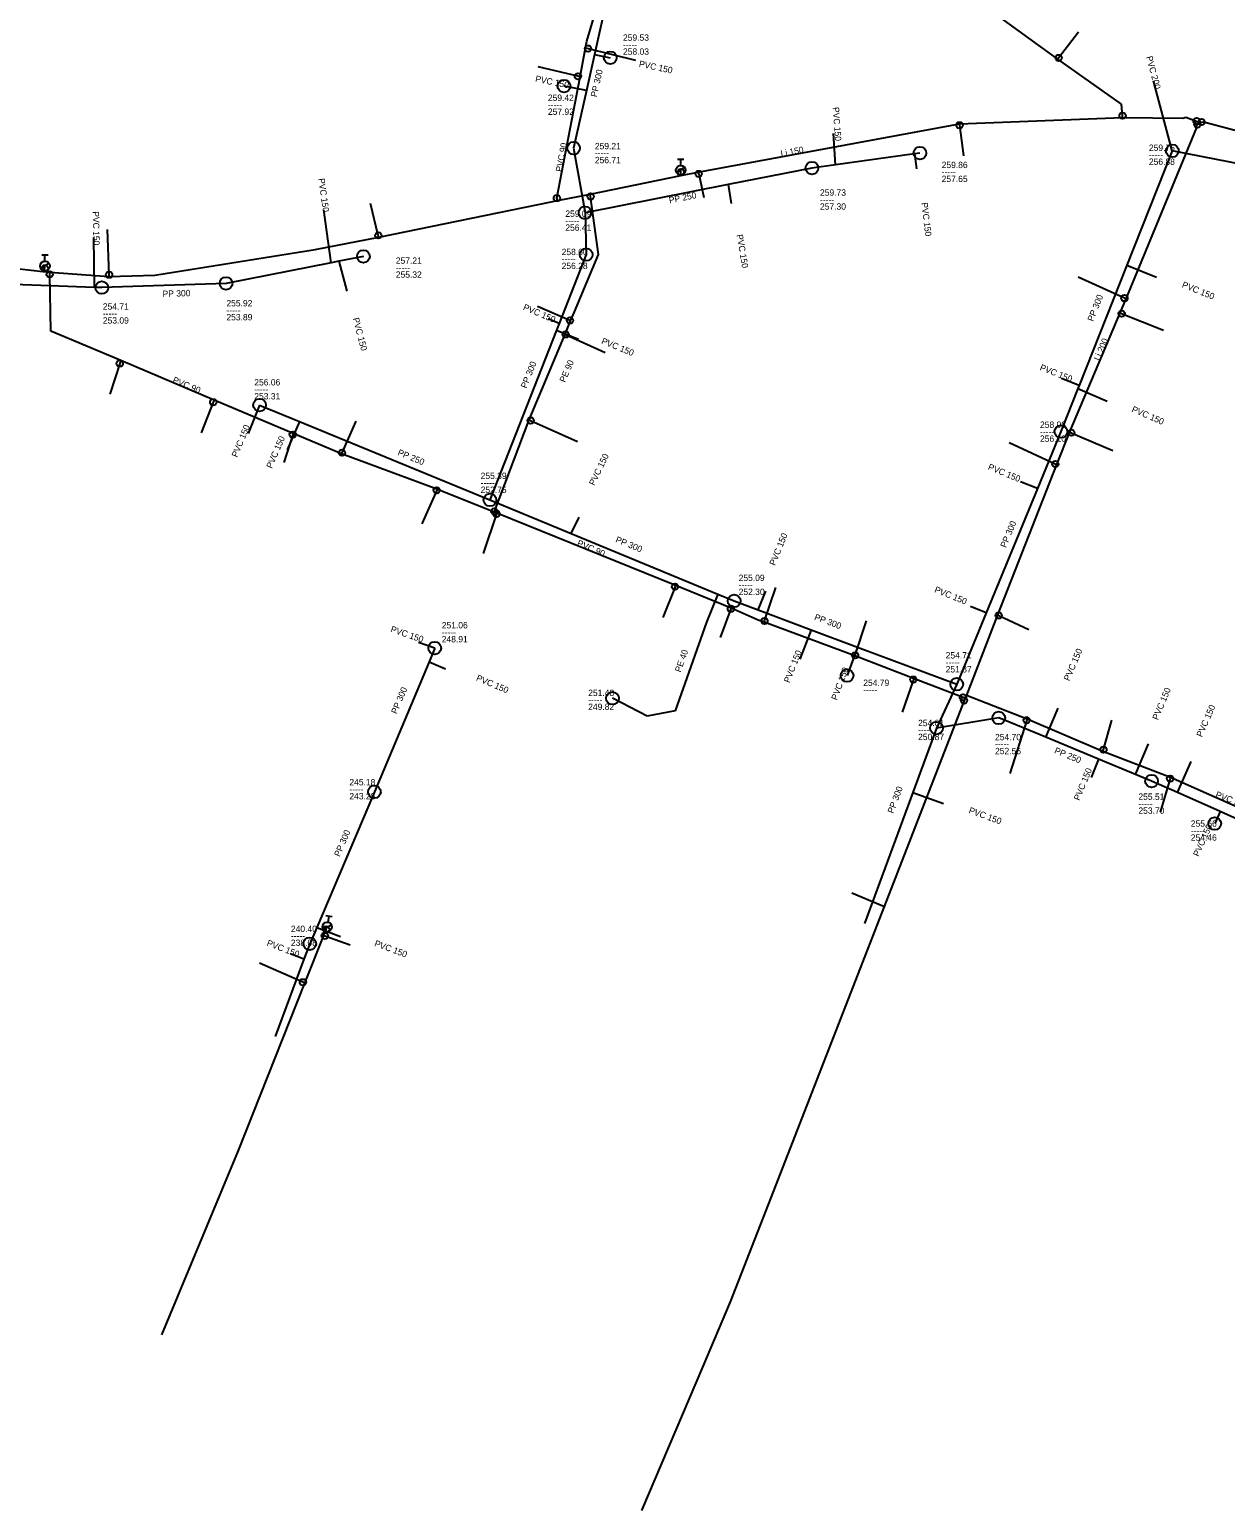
# Model space of a CAD drawing. Extents: x -771681 to -770485, y -1050143 to -1049574.
# Drawn here: x -771090.5 to -770902.2, y -1050131.9 to -1049898.6 of the extents above; entities that cross this region are included whole.
import ezdxf

# ---------------------------------------------------------------- set-up
doc = ezdxf.new("R2010")
doc.units = 0
doc.layers.add('Level 0', color=7, linetype='Continuous')

msp = doc.modelspace()

# ---------------------------------------------------------------- linework, layer by layer
at = {"layer": 'Level 0'}
for p, q in [((-770928.56, -1049903.22), (-770958.39, -1049881.57)), ((-771002.75, -1049900.38), (-770999.4, -1049889.07)), ((-770999.32, -1049892.41), (-771001.56, -1049902.49)), ((-770928.44, -1049903.02), (-770925.29, -1049898.94)), ((-771003.82, -1049906), (-771002.95, -1049901.45)), ((-771002.95, -1049901.45), (-771002.75, -1049900.38)), ((-771002.95, -1049901.45), (-771002.55, -1049901.55)), ((-771002.55, -1049901.55), (-770995.09, -1049903.36)), ((-771004.15, -1049905.92), (-771010.41, -1049904.41)), ((-771001.56, -1049902.49), (-771002.82, -1049908.17)), ((-771001.56, -1049902.49), (-770999.06, -1049903.01)), ((-770928.56, -1049903.22), (-770928.44, -1049903.02)), ((-770918.52, -1049910.31), (-770928.56, -1049903.22)), ((-771007.46, -1049925.12), (-771003.82, -1049906)), ((-771003.82, -1049906), (-771004.15, -1049905.92)), ((-770910.53, -1049917.67), (-770913.49, -1049906.66)), ((-771002.82, -1049908.17), (-771006.34, -1049907.46)), ((-771002.82, -1049908.17), (-771004.84, -1049917.25)), ((-770918.37, -1049912.13), (-770918.52, -1049910.31)), ((-770985.26, -1049921.04), (-770944.04, -1049913.41)), ((-770944.04, -1049913.41), (-770944.05, -1049913.63)), ((-770944.05, -1049913.63), (-770943.4, -1049918.48)), ((-770944.04, -1049913.41), (-770918.39, -1049912.4)), ((-770918.39, -1049912.4), (-770918.37, -1049912.13)), ((-770918.39, -1049912.4), (-770908.88, -1049912.5)), ((-770906.72, -1049913.97), (-770917.83, -1049940.99)), ((-770908.88, -1049912.5), (-770908.38, -1049912.34)), ((-770908.38, -1049912.34), (-770906.71, -1049912.99)), ((-770906.58, -1049913.53), (-770906.72, -1049913.63)), ((-770906.72, -1049913.63), (-770906.72, -1049913.97)), ((-770906.71, -1049912.99), (-770906.33, -1049913.19)), ((-770906.33, -1049913.19), (-770906.58, -1049913.53)), ((-770906.33, -1049913.19), (-770905.9, -1049913.13)), ((-770905.9, -1049913.13), (-770905.79, -1049913.08)), ((-770905.79, -1049913.08), (-770905.19, -1049913.2)), ((-770905.19, -1049913.2), (-770899.25, -1049914.79)), ((-770963.57, -1049919.87), (-770963.92, -1049914.94)), ((-771004.84, -1049917.25), (-771003.03, -1049927.43)), ((-770951.12, -1049918.13), (-770963.57, -1049919.87)), ((-770950.29, -1049918.02), (-770951.12, -1049918.13)), ((-770951.12, -1049918.13), (-770950.83, -1049920.48)), ((-770910.53, -1049917.67), (-770917.68, -1049935.69)), ((-770886.57, -1049922.39), (-770910.53, -1049917.67)), ((-770988.55, -1049921.18), (-770987.37, -1049920.26)), ((-770988.46, -1049918.97), (-770987.46, -1049918.97)), ((-770987.96, -1049919.97), (-770987.96, -1049918.97)), ((-770987.95, -1049921.03), (-770987.96, -1049920.72)), ((-770987.93, -1049921.58), (-770987.95, -1049921.03)), ((-770987.93, -1049921.58), (-770985.26, -1049921.04)), ((-770985.26, -1049921.04), (-770985.13, -1049921.3)), ((-770967.3, -1049920.39), (-770980.5, -1049922.99)), ((-770963.57, -1049919.87), (-770967.3, -1049920.39)), ((-770980.5, -1049922.99), (-771003.03, -1049927.43)), ((-771002.22, -1049924.48), (-770987.93, -1049921.58)), ((-770985.13, -1049921.3), (-770984.32, -1049925)), ((-770980.5, -1049922.99), (-770980, -1049925.95)), ((-771035.53, -1049931.25), (-771008.36, -1049925.72)), ((-771008.36, -1049925.72), (-771007.38, -1049925.52)), ((-771007.38, -1049925.52), (-771007.46, -1049925.12)), ((-771007.38, -1049925.52), (-771002.22, -1049924.48)), ((-771002.15, -1049924.86), (-771002.22, -1049924.48)), ((-771000.93, -1049934), (-771002.15, -1049924.86)), ((-771043.02, -1049935.3), (-771044.18, -1049926.99)), ((-771035.59, -1049930.99), (-771036.81, -1049925.98)), ((-771003.03, -1049927.43), (-771002.85, -1049934.01)), ((-771077.98, -1049937.2), (-771078.25, -1049930.04)), ((-771080.29, -1049939.18), (-771080.41, -1049931.3)), ((-771045.53, -1049933.22), (-771035.53, -1049931.25)), ((-771035.53, -1049931.25), (-771035.59, -1049930.99)), ((-771107.19, -1049934.56), (-771088.4, -1049936.68)), ((-771088.59, -1049934.07), (-771087.59, -1049934.07)), ((-771088.09, -1049935.07), (-771088.09, -1049934.07)), ((-771070.78, -1049937.27), (-771045.53, -1049933.22)), ((-771041.79, -1049935.06), (-771043.02, -1049935.3)), ((-771037.93, -1049934.3), (-771041.79, -1049935.06)), ((-771041.79, -1049935.06), (-771040.55, -1049939.76)), ((-771002.85, -1049934.01), (-771007.12, -1049944.9)), ((-771004.7, -1049943.05), (-771000.93, -1049934)), ((-771088.68, -1049936.28), (-771087.5, -1049935.36)), ((-771088.4, -1049936.68), (-771088.11, -1049936.17)), ((-771088.4, -1049936.68), (-771087.31, -1049936.77)), ((-771088.11, -1049936.17), (-771088.09, -1049935.82)), ((-771087.34, -1049937.13), (-771087.31, -1049936.77)), ((-771087.19, -1049946.08), (-771087.34, -1049937.13)), ((-771087.31, -1049936.77), (-771078.01, -1049937.45)), ((-771078.01, -1049937.45), (-771077.98, -1049937.2)), ((-771078.01, -1049937.45), (-771070.78, -1049937.27)), ((-771043.02, -1049935.3), (-771059.57, -1049938.57)), ((-770917.68, -1049935.69), (-770925.18, -1049954.62)), ((-770917.68, -1049935.69), (-770913.04, -1049937.56)), ((-771080.29, -1049939.18), (-771098.77, -1049938.52)), ((-771079.13, -1049939.22), (-771080.29, -1049939.18)), ((-771059.57, -1049938.57), (-771079.13, -1049939.22)), ((-770918.07, -1049940.88), (-770925.37, -1049937.57)), ((-770917.83, -1049940.99), (-770918.78, -1049943.21)), ((-770917.83, -1049940.99), (-770918.07, -1049940.88)), ((-771005.4, -1049944.4), (-771010.49, -1049942.2)), ((-771007.12, -1049944.9), (-771008.86, -1049944.16)), ((-771005.3, -1049944.44), (-771004.7, -1049943.05)), ((-770918.78, -1049943.21), (-770926.75, -1049961.95)), ((-770918.78, -1049943.21), (-770918.51, -1049943.32)), ((-770918.51, -1049943.32), (-770911.91, -1049945.95)), ((-771076.16, -1049950.73), (-771087.19, -1049946.08)), ((-771007.53, -1049945.94), (-771018, -1049972.67)), ((-771011.82, -1049960.05), (-771006.17, -1049946.56)), ((-771007.12, -1049944.9), (-771007.53, -1049945.94)), ((-771007.53, -1049945.94), (-771004.08, -1049947.35)), ((-771006.17, -1049946.56), (-771005.3, -1049944.44)), ((-771006.17, -1049946.56), (-771006.08, -1049946.6)), ((-771006.08, -1049946.6), (-770999.85, -1049949.42)), ((-771005.3, -1049944.44), (-771005.4, -1049944.4)), ((-771076.3, -1049951.17), (-771077.85, -1049956.03)), ((-771076.16, -1049950.73), (-771076.3, -1049951.17)), ((-771061.45, -1049956.94), (-771076.16, -1049950.73)), ((-770925.18, -1049954.62), (-770927.96, -1049953.52)), ((-770925.39, -1049955.14), (-770928.07, -1049961.9)), ((-770925.18, -1049954.62), (-770925.39, -1049955.14)), ((-770925.39, -1049955.14), (-770920.8, -1049957.11)), ((-771061.59, -1049957.28), (-771063.49, -1049962.08)), ((-771061.45, -1049956.94), (-771061.59, -1049957.28)), ((-771048.99, -1049962.2), (-771061.45, -1049956.94)), ((-771054.29, -1049957.73), (-771056.11, -1049962.19)), ((-771054.29, -1049957.73), (-771048.02, -1049960.31)), ((-771048.02, -1049960.31), (-771049.92, -1049964.77)), ((-771048.02, -1049960.31), (-771018, -1049972.67)), ((-771041.3, -1049965.23), (-771039.05, -1049960.29)), ((-771017.31, -1049974.48), (-771011.82, -1049960.05)), ((-771011.82, -1049960.05), (-771011.6, -1049960.17)), ((-771011.6, -1049960.17), (-771004.2, -1049963.48)), ((-771049.05, -1049962.39), (-771050.49, -1049966.79)), ((-771048.99, -1049962.2), (-771049.05, -1049962.39)), ((-771041.38, -1049965.4), (-771048.99, -1049962.2)), ((-770928.07, -1049961.9), (-770931.78, -1049970.89)), ((-770926.75, -1049961.95), (-770928.77, -1049967.11)), ((-770926.75, -1049961.95), (-770926.45, -1049962.08)), ((-770926.45, -1049962.08), (-770919.88, -1049964.9)), ((-771041.38, -1049965.4), (-771041.3, -1049965.23)), ((-770928.96, -1049967.02), (-770936.22, -1049963.66)), ((-771026.35, -1049970.97), (-771041.38, -1049965.4)), ((-770928.77, -1049967.11), (-770938.08, -1049990.78)), ((-770928.77, -1049967.11), (-770928.96, -1049967.02)), ((-770931.78, -1049970.89), (-770934.43, -1049969.8)), ((-771026.39, -1049971.16), (-771028.73, -1049976.44)), ((-771026.35, -1049970.97), (-771026.39, -1049971.16)), ((-771017.35, -1049974.59), (-771026.35, -1049970.97)), ((-770931.78, -1049970.89), (-770939.86, -1049990.46)), ((-771018, -1049972.67), (-771005.19, -1049977.97)), ((-771017.35, -1049974.59), (-771017.31, -1049974.48)), ((-771016.93, -1049974.76), (-771017.35, -1049974.59)), ((-771016.97, -1049974.87), (-771019.09, -1049981.13)), ((-771016.93, -1049974.76), (-771016.97, -1049974.87)), ((-770988.88, -1049986.08), (-771016.93, -1049974.76)), ((-771005.19, -1049977.97), (-771003.95, -1049975.39)), ((-771005.19, -1049977.97), (-770982.12, -1049987.51)), ((-770988.85, -1049986.35), (-770990.77, -1049991.18)), ((-770988.88, -1049986.08), (-770988.85, -1049986.35)), ((-770980.03, -1049989.74), (-770988.88, -1049986.08)), ((-770982.12, -1049987.51), (-770983.91, -1049991.92)), ((-770982.12, -1049987.51), (-770979.54, -1049988.58)), ((-770979.54, -1049988.58), (-770975.75, -1049990)), ((-770975.75, -1049990), (-770974.55, -1049987.05)), ((-770974.77, -1049991.74), (-770972.97, -1049986.45)), ((-770980.06, -1049989.83), (-770981.76, -1049994.37)), ((-770980.03, -1049989.74), (-770980.06, -1049989.83)), ((-770975.76, -1049991.6), (-770980.03, -1049989.74)), ((-770975.75, -1049990), (-770967.39, -1049993.13)), ((-770939.86, -1049990.46), (-770944.48, -1050001.71)), ((-770938.08, -1049990.78), (-770942.97, -1050003.46)), ((-770939.86, -1049990.46), (-770942.31, -1049989.46)), ((-770938.08, -1049990.78), (-770937.87, -1049990.88)), ((-770937.87, -1049990.88), (-770933.14, -1049993.08)), ((-770983.91, -1049991.92), (-770988.82, -1050005.91)), ((-770974.84, -1049991.95), (-770975.76, -1049991.6)), ((-770974.84, -1049991.95), (-770974.77, -1049991.74)), ((-770960.52, -1049997.25), (-770974.84, -1049991.95)), ((-770967.39, -1049993.13), (-770969.22, -1049997.76)), ((-770967.39, -1049993.13), (-770960.1, -1049995.86)), ((-770960.49, -1049997.16), (-770958.68, -1049991.73)), ((-771026.69, -1049996.02), (-771029.28, -1049995.14)), ((-771026.69, -1049996.02), (-771027.6, -1049998.19)), ((-770960.1, -1049995.86), (-770961.76, -1050000.36)), ((-770960.52, -1049997.25), (-770960.49, -1049997.16)), ((-770951.27, -1050000.82), (-770960.52, -1049997.25)), ((-770960.1, -1049995.86), (-770944.48, -1050001.71)), ((-771027.6, -1049998.19), (-771036.2, -1050018.67)), ((-771027.6, -1049998.19), (-771024.99, -1049999.3)), ((-770951.32, -1050000.98), (-770953.07, -1050006.13)), ((-770951.27, -1050000.82), (-770951.32, -1050000.98)), ((-770943.49, -1050003.79), (-770951.27, -1050000.82)), ((-770944.48, -1050001.71), (-770947.67, -1050008.62)), ((-770993.25, -1050006.75), (-770998.7, -1050003.93)), ((-770943.34, -1050004.29), (-770955.89, -1050036.76)), ((-770943.15, -1050003.92), (-770943.49, -1050003.79)), ((-770943.15, -1050003.92), (-770943.34, -1050004.29)), ((-770943.06, -1050003.69), (-770943.15, -1050003.92)), ((-770942.97, -1050003.46), (-770943.06, -1050003.69)), ((-770942.97, -1050003.46), (-770933.39, -1050007.15)), ((-770988.82, -1050005.91), (-770993.25, -1050006.75)), ((-770937.86, -1050007.02), (-770947.67, -1050008.62)), ((-770930.45, -1050010.07), (-770937.86, -1050007.02)), ((-770933.46, -1050007.39), (-770936.1, -1050015.78)), ((-770933.39, -1050007.15), (-770933.46, -1050007.39)), ((-770933.39, -1050007.15), (-770921.45, -1050012.26)), ((-770930.45, -1050010.07), (-770928.49, -1050005.49)), ((-770947.67, -1050008.62), (-770951.41, -1050018.75)), ((-770921.38, -1050012.02), (-770920.06, -1050007.4)), ((-770922.15, -1050013.52), (-770930.45, -1050010.07)), ((-770921.45, -1050012.26), (-770921.38, -1050012.02)), ((-770916.33, -1050015.93), (-770914.3, -1050011.1)), ((-770922.15, -1050013.52), (-770923.32, -1050016.39)), ((-770916.33, -1050015.93), (-770922.15, -1050013.52)), ((-770921.45, -1050012.26), (-770910.81, -1050016.36)), ((-770909.74, -1050018.79), (-770907.57, -1050013.91)), ((-770913.79, -1050016.98), (-770916.33, -1050015.93)), ((-770910.88, -1050016.59), (-770912.45, -1050021.89)), ((-770910.81, -1050016.36), (-770910.88, -1050016.59)), ((-770910.81, -1050016.36), (-770888.36, -1050026.38)), ((-771036.2, -1050018.67), (-771045.29, -1050040.05)), ((-770951.41, -1050018.75), (-770959.03, -1050039.42)), ((-770951.41, -1050018.75), (-770946.57, -1050020.53)), ((-770909.74, -1050018.79), (-770913.79, -1050016.98)), ((-770903.01, -1050021.79), (-770909.74, -1050018.79)), ((-770903.01, -1050021.79), (-770903.85, -1050023.68)), ((-770888.9, -1050028.09), (-770903.01, -1050021.79)), ((-770956.12, -1050036.66), (-770961.03, -1050034.64)), ((-770955.89, -1050036.76), (-770974.18, -1050083.68)), ((-770955.89, -1050036.76), (-770956.12, -1050036.66)), ((-771045.29, -1050040.05), (-771046.38, -1050042.61)), ((-771045.29, -1050040.05), (-771041.55, -1050041.44)), ((-771044.3, -1050040.31), (-771042.98, -1050039.61)), ((-771043.83, -1050038.15), (-771042.84, -1050038.32)), ((-771043.79, -1050040.33), (-771043.64, -1050039.96)), ((-771043.51, -1050039.22), (-771043.34, -1050038.24)), ((-771047.15, -1050048.81), (-771044.18, -1050041.31)), ((-771044.18, -1050041.31), (-771043.79, -1050040.33)), ((-771044.18, -1050041.31), (-771044.01, -1050041.37)), ((-771044.01, -1050041.37), (-771040.03, -1050042.8)), ((-771047.3, -1050045.03), (-771049.44, -1050044.22)), ((-771046.38, -1050042.61), (-771047.3, -1050045.03)), ((-771047.47, -1050048.67), (-771054.3, -1050045.66)), ((-771047.3, -1050045.03), (-771051.85, -1050057.23)), ((-771057.63, -1050075.21), (-771047.15, -1050048.81)), ((-771047.15, -1050048.81), (-771047.47, -1050048.67)), ((-771069.66, -1050104.23), (-771057.63, -1050075.21)), ((-770974.18, -1050083.68), (-770980.16, -1050099.05)), ((-770980.16, -1050099.05), (-770984.54, -1050109.33)), ((-770984.54, -1050109.33), (-770994.14, -1050131.89))]:
    msp.add_line(p, q, dxfattribs=at)
for centre, radius in [((-771002.55, -1049901.55), 0.5), ((-770999.06, -1049903.01), 1), ((-770928.44, -1049903.02), 0.5), ((-771006.34, -1049907.46), 1), ((-771004.15, -1049905.92), 0.5), ((-770918.37, -1049912.13), 0.5), ((-770944.05, -1049913.63), 0.5), ((-770906.71, -1049912.99), 0.5), ((-770906.58, -1049913.53), 0.5), ((-770905.9, -1049913.13), 0.5), ((-771004.84, -1049917.25), 1), ((-770950.29, -1049918.02), 1), ((-770910.53, -1049917.67), 1), ((-770987.96, -1049920.72), 0.75), ((-770987.95, -1049921.03), 0.5), ((-770985.13, -1049921.3), 0.5), ((-770967.3, -1049920.39), 1), ((-771007.46, -1049925.12), 0.5), ((-771002.15, -1049924.86), 0.5), ((-771003.03, -1049927.43), 1), ((-771035.59, -1049930.99), 0.5), ((-771037.93, -1049934.3), 1), ((-771002.85, -1049934.01), 1), ((-771088.09, -1049935.82), 0.75), ((-771088.11, -1049936.17), 0.5), ((-771087.34, -1049937.13), 0.5), ((-771077.98, -1049937.2), 0.5), ((-771079.13, -1049939.22), 1), ((-771059.57, -1049938.57), 1), ((-770918.07, -1049940.88), 0.5), ((-771005.39, -1049944.4), 0.5), ((-770918.51, -1049943.32), 0.5), ((-771006.08, -1049946.6), 0.5), ((-771076.3, -1049951.17), 0.5), ((-771061.59, -1049957.28), 0.5), ((-771054.29, -1049957.73), 1), ((-771011.6, -1049960.17), 0.5), ((-771049.05, -1049962.39), 0.5), ((-770928.07, -1049961.9), 1), ((-770926.45, -1049962.08), 0.5), ((-771041.3, -1049965.23), 0.5), ((-770928.96, -1049967.02), 0.5), ((-771026.39, -1049971.16), 0.5), ((-771018, -1049972.67), 1), ((-771017.31, -1049974.48), 0.5), ((-771016.97, -1049974.87), 0.5), ((-770988.85, -1049986.35), 0.5), ((-770979.54, -1049988.58), 1), ((-770980.06, -1049989.83), 0.5), ((-770937.87, -1049990.88), 0.5), ((-770974.77, -1049991.74), 0.5), ((-771026.69, -1049996.02), 1), ((-770960.49, -1049997.16), 0.5), ((-770961.76, -1050000.36), 1), ((-770951.32, -1050000.98), 0.5), ((-770944.48, -1050001.71), 1), ((-770998.7, -1050003.93), 1), ((-770943.49, -1050003.79), 0.5), ((-770943.34, -1050004.29), 0.5), ((-770937.86, -1050007.02), 1), ((-770933.46, -1050007.39), 0.5), ((-770947.67, -1050008.62), 1), ((-770921.38, -1050012.02), 0.5), ((-770913.79, -1050016.98), 1), ((-770910.88, -1050016.59), 0.5), ((-771036.2, -1050018.67), 1), ((-770903.85, -1050023.68), 1), ((-771043.64, -1050039.96), 0.75), ((-771043.79, -1050040.33), 0.5), ((-771046.38, -1050042.61), 1), ((-771044.01, -1050041.37), 0.5), ((-771047.47, -1050048.67), 0.5)]:
    msp.add_circle(centre, radius, dxfattribs=at)

# ---------------------------------------------------------------- texts
for s, p in [('259.53', (-770997.05, -1049900.33)), ('-----', (-770997.05, -1049901.43)), ('258.03', (-770997.05, -1049902.53)), ('259.42', (-771008.88, -1049909.8)), ('-----', (-771008.88, -1049910.9)), ('257.92', (-771008.88, -1049912)), ('-----', (-771001.48, -1049918.52)), ('259.21', (-771001.48, -1049917.42)), ('256.71', (-771001.48, -1049919.62)), ('-----', (-770914.22, -1049918.78)), ('259.75', (-770914.22, -1049917.68)), ('-----', (-770946.86, -1049921.49)), ('259.86', (-770946.86, -1049920.39)), ('256.88', (-770914.22, -1049919.88)), ('257.65', (-770946.86, -1049922.59)), ('-----', (-770966.02, -1049925.84)), ('259.73', (-770966.02, -1049924.74)), ('259.09', (-771006.13, -1049928.07)), ('257.30', (-770966.02, -1049926.94)), ('-----', (-771006.13, -1049929.17)), ('256.41', (-771006.13, -1049930.27)), ('257.21', (-771032.83, -1049935.47)), ('-----', (-771006.71, -1049935.2)), ('258.60', (-771006.71, -1049934.1)), ('-----', (-771032.83, -1049936.57)), ('255.32', (-771032.83, -1049937.67)), ('256.28', (-771006.71, -1049936.3)), ('254.71', (-771078.97, -1049942.69)), ('255.92', (-771059.51, -1049942.18)), ('-----', (-771078.97, -1049943.79)), ('253.09', (-771078.97, -1049944.89)), ('-----', (-771059.51, -1049943.28)), ('253.89', (-771059.51, -1049944.38)), ('256.06', (-771055.12, -1049954.64)), ('-----', (-771055.12, -1049955.74)), ('253.31', (-771055.12, -1049956.84)), ('258.08', (-770931.37, -1049961.32)), ('-----', (-770931.37, -1049962.42)), ('256.10', (-770931.37, -1049963.52)), ('-----', (-771019.47, -1049970.47)), ('255.39', (-771019.47, -1049969.37)), ('252.75', (-771019.47, -1049971.57)), ('-----', (-770978.83, -1049986.55)), ('255.09', (-770978.83, -1049985.45)), ('252.30', (-770978.83, -1049987.65)), ('251.06', (-771025.59, -1049992.92)), ('-----', (-771025.59, -1049994.02)), ('248.91', (-771025.59, -1049995.12)), ('254.71', (-770946.23, -1049997.66)), ('-----', (-770946.23, -1049998.76)), ('251.87', (-770946.23, -1049999.86)), ('251.48', (-771002.53, -1050003.57)), ('-----', (-770959.21, -1050003.08)), ('254.79', (-770959.21, -1050001.98)), ('-----', (-771002.53, -1050004.67)), ('249.82', (-771002.53, -1050005.77)), ('254.01', (-770950.57, -1050008.32)), ('-----', (-770950.57, -1050009.42)), ('250.87', (-770950.57, -1050010.52)), ('254.70', (-770938.45, -1050010.54)), ('-----', (-770938.45, -1050011.64)), ('252.55', (-770938.45, -1050012.74)), ('245.18', (-771040.14, -1050017.65)), ('-----', (-771040.14, -1050018.75)), ('243.28', (-771040.14, -1050019.85)), ('255.51', (-770915.87, -1050019.93)), ('-----', (-770915.87, -1050021.03)), ('253.70', (-770915.87, -1050022.13)), ('255.66', (-770907.62, -1050024.17)), ('-----', (-770907.62, -1050025.27)), ('254.46', (-770907.62, -1050026.37)), ('240.40', (-771049.35, -1050040.75)), ('-----', (-771049.35, -1050041.85)), ('238.08', (-771049.35, -1050042.95))]:
    msp.add_text(s, height=1, dxfattribs=at).set_placement(p)
for s, rotation, p in [('PVC 150', 348.25, (-770994.6, -1049904.41)), ('PVC 200', 285.048, (-770914.67, -1049902.88)), ('PVC 150', 348.596, (-771010.93, -1049906.76)), ('PP 300', 77.493, (-771001.18, -1049909.26)), ('PVC 150', 274.061, (-770964.02, -1049910.81)), ('PVC 90', 79.413, (-771006.68, -1049921.04)), ('Li 150', 10.487, (-770972.12, -1049918.61)), ('PVC 150', 277.947, (-771045.04, -1049922.06)), ('PP 250', 11.143, (-770989.71, -1049925.96)), ('PVC 150', 270.872, (-771080.56, -1049927.21)), ('PVC 150', 277.035, (-770950.08, -1049925.87)), ('PVC 150', 279.588, (-770979.17, -1049930.92)), ('PP 300', 1.903, (-771069.55, -1049940.71)), ('PVC 150', 338.05, (-770909.11, -1049939.14)), ('PVC 150', 336.961, (-771012.87, -1049942.68)), ('PP 300', 68.387, (-770923.01, -1049944.64)), ('PVC 150', 284.78, (-771039.63, -1049944.09)), ('PVC 150', 337.77, (-771000.54, -1049948.01)), ('Li 200', 66.96, (-770922.02, -1049950.82)), ('PP 300', 68.484, (-771012.26, -1049955.18)), ('PE 90', 66.652, (-771006.18, -1049954.25)), ('PVC 150', 338.412, (-770931.49, -1049952.18)), ('PVC 90', 337.113, (-771068.08, -1049954.14)), ('PVC 150', 336.771, (-770917.03, -1049958.76)), ('PVC 150', 67.801, (-771057.8, -1049966.05)), ('PVC 150', 66.926, (-771052.35, -1049967.8)), ('PP 250', 337.622, (-771032.63, -1049965.57)), ('PVC 150', 64.33, (-771001.56, -1049970.5)), ('PVC 150', 337.642, (-770939.66, -1049967.85)), ('PP 300', 67.565, (-770936.74, -1049980.29)), ('PVC 90', 336.462, (-771004.38, -1049979.83)), ('PP 300', 337.534, (-770998.32, -1049979.3)), ('PVC 150', 67.865, (-770973.11, -1049983.1)), ('PVC 150', 337.797, (-770948.09, -1049987.18)), ('PP 300', 339.47, (-770967, -1049991.53)), ('PVC 150', 341.234, (-771033.74, -1049993.45)), ('PE 40', 70.55, (-770987.97, -1049999.91)), ('PVC 150', 68.434, (-770970.83, -1050001.58)), ('PVC 150', 66.832, (-770926.76, -1050001.28)), ('PVC 150', 336.961, (-771020.26, -1050001.09)), ('PVC 150', 69.752, (-770963.35, -1050004.31)), ('PP 300', 67.249, (-771032.69, -1050006.48)), ('PVC 150', 67.203, (-770912.8, -1050007.44)), ('PVC 150', 66.027, (-770905.88, -1050010.12)), ('PP 250', 337.506, (-770929.2, -1050012.53)), ('PVC 150', 67.821, (-770925.17, -1050020.13)), ('PP 300', 69.764, (-770954.48, -1050022.15)), ('PVC 90', 338.926, (-770903.82, -1050019.48)), ('PVC 150', 339.808, (-770942.68, -1050021.98)), ('PP 300', 66.967, (-771041.67, -1050028.97)), ('PVC 150', 66.038, (-770906.39, -1050028.95)), ('PVC 150', 339.268, (-771053.25, -1050042.89)), ('PVC 150', 339.612, (-771036.29, -1050042.94))]:
    msp.add_text(s, height=1, rotation=rotation, dxfattribs=at).set_placement(p)

doc.saveas('drawing.dxf')
